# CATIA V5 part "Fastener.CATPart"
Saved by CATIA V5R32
Part number: Fastener
Bounding box of the stored display mesh (mm): x -4.826 to 4.826, y -4.826 to 4.826, z -47.752 to 0
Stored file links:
  D:\PROJECTS\Project 2022\CATIA V5 6R 2022\Resources\Part Files\c13_catia_v5_6r2022_prt\c13_catia_v5-6r2022_figr_13-45\Part & Asm files\Fastener.CATPart
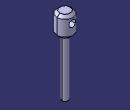
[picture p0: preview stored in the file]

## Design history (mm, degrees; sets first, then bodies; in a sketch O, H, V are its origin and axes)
Body1 (main body)
  Sketch1 on xy-plane, origin (0, 0, 0), H (1, 0, 0), V (0, 1, 0)
    circle A1 centre (0, 0) radius 4.826
    circle A2 centre (0, 0) radius 1.905
    radius A2 = 1.905
    radius A1 = 4.826
  MultiPad1: profile Sketch1, domains (length 0 / length 47.752; length 0 / length 12.7)
  Chamfer1: length 1.5875, angle 45, on 2 edges
  Chamfer2: length 0.508, angle 45, on 1 edge
  Sketch2 on zx-plane, origin (-1.612, 0, 1.612), H (1, 0, 0), V (0, 0, -1)
    point P1 (1.612, 6.35)
    reference intersected line E1 through (1.612, 0) direction (0, 1) from yz-plane
    distance P1 H = 6.35
    coincidence: E1 P1
  Hole1: placed by Sketch2, at (0, 0, -4.738) direction (0, -1, 0), diameter 4.064, depth 10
